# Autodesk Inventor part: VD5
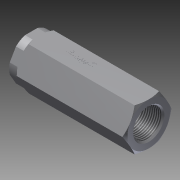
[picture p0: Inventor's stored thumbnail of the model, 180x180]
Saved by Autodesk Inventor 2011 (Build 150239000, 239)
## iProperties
Created: 2012-01
Part Number: VD5
Document SubType Name: Modeling
Designer: khramov
Density: 1 g/cm^3
Author: khramov
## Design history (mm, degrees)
derived "VD5_W1_30.ipt"
feature "Твердое тело1::VD5_W1_30.ipt" dims "d0" = 10
tag "Элемент создания маркировки1"
node "Твердое тело1"
